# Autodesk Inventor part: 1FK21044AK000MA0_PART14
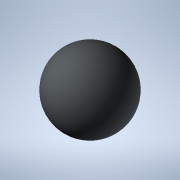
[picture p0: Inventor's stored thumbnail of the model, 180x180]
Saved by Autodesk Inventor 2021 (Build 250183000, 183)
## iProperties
Created: 2025-04
Part Number: 1FK21044AK000MA0_PART14
Material: Generic
Catalog Web Link: www.3dfindit.com
Description: -Servo synchronous motor
Document SubType Name: Modeling
Designer: psAdmin
Mass: 0.137258 g
Surface Area: 1.2868 cm^2
Volume: 0.137258 cm^3
Density: 1 g/cm^3
Appearance: PSOLRGB-212-217-219
Category: PARTsolutions
Title: 1FK21044AK000MA0_PART14
Author: Cadenas PARTsolutions
Comments: Servo synchronous motor
Sending System: PARTsolutions
Preprocessor: ST-DEVELOPER v19.3
PSOL_IDENT_0: {$CADENAS_DATA/23d-libs/siemens_ag/_cat_/87/f4/1fk21044ak000ma0.prj},216 {VTYP=3D},{NB=1FK21044AK000
PSOL_IDENT_1: MA0_PART14},{LINA=1FK21044AK000MA0_PART14},{NN=1FK21044AK000MA0_PART14},{NOPRJ=TRUE},{DATE=19.08.202
PSOL_IDENT_2: 5 14:00:48},{GEOMDATE=30.07.2025 02:00:50},{VERSION=},{LINEID=10},{WBVAR=},{WBNUMERIC=}  {NB=1FK2104
PSOL_IDENT_3: 4AK000MA0_PART14},{LINA=1FK21044AK000MA0_PART14},{KT=DUMMY},{PREVIEW=../../../_pool_/cb/72/p_d211_xx
PSOL_IDENT_4: _00434j.png},{DESCSHORT=SIMOTICS S-1FK2 HD, SINAMICS S210 3AC 400V-480V, 0.95 Nm, 6000 rpm},{DESCLON
PSOL_IDENT_5: G=SIMOTICS S-1FK2 HD servo motor M0=1.27 Nm; PN = 0.6 kW at nN=6000 rpm (380-480 V); PN = 0.4 kW at
PSOL_IDENT_6: nN=3000 rpm (200-240 V); degree of protection IP64; cylindrical shaft D19x40mm; absolute encoder 22-
PSOL_IDENT_7: bit + 12-bit multiturn (encoder AM22DQC); with OCC interface; plug size M17, rotatable; SIMOTICS S-1
PSOL_IDENT_8: FK2 servomotorfor a wide range of uses in industrial environments. SIMOTICS S‑1FK2 servomotors are c
PSOL_IDENT_9: ompact synchronous motors with a high dynamic performance that set themselves apart as a result of t
PSOL_IDENT_10: heir high power density, degree of protection and overload capability. The motors are available in t
PSOL_IDENT_11: wo variants: as High Dynamic variant (highest dynamic performance as a result of the low intrinsic m
PSOL_IDENT_12: oment of inertia for applications demanding a high dynamic performance with low moved masses) - and
PSOL_IDENT_13: as Compact variant (precise and stable closed-loop control for medium up to large moved masses as a
PSOL_IDENT_14: result of a medium intrinsic moment of inertia). SIMOTICSS‑1FK2 servomotors fully exploit their stre
PSOL_IDENT_15: ngths in a system with the SINAMICSS210 frequency converter and simple connection using the one cabl
PSOL_IDENT_16: e connection (OCC). Advantages include the short control and positioning times, fast and precise cor
PSOL_IDENT_17: rection of disturbing quantities as well as stable control with a high dynamic performance. The serv
PSOL_IDENT_18: o motors can be configured to address a wide range of requirements. For example with and without hol
PSOL_IDENT_19: ding brake, IP64 or IP65 degree of protection, singleturn or multiturn absolute encoders - to name j
PSOL_IDENT_20: ust a few. Further, the servomotors are available in different shaft heights extending from 20 to 10
PSOL_IDENT_21: 0. A shaft sealing ring is available to achieve an IP65 degree of protection and for subsequent moun
PSOL_IDENT_22: ting at the motor or as spare part. SIMOTICS - the optimum motor for each and every motion control a
PSOL_IDENT_23: pplication.},{INTNO=195125056312},{SUPPLIERALTNO=1FK2104-4AK00-0MA0},{MANUID=1FK21044AK000MA0},{MANU
PSOL_IDENT_24: NAME=Siemens},{MANUTYPEDESC=Synchronous motor 1FK2-HD 1,27 Nm},{AAU732=SIMOTICS},{AAO057=S-1FK2},{AA
PSOL_IDENT_25: U734=SIMOTICS S-1FK2 HD servo motor M0=1.27 Nm; PN = 0.6 kW at nN=6000 rpm (380-480 V); PN = 0.4 kW
PSOL_IDENT_26: at nN=3000 rpm (200-240 V); degree of protection IP64; cylindrical shaft D19x40mm; absolute encoder
PSOL_IDENT_27: 22-bit + 12-bit multiturn (encoder AM22DQC); with OCC interface; plug size M17, rotatable;},{AAW338=
PSOL_IDENT_28: Synchronous motor 1FK2-HD 1,27 Nm},{AAO742=SIMOTICS},{AAO663=4042948690994},{NOCUPEROU=1},{PRICEQUAN
PSOL_IDENT_29: TITY=1},{QUANTITYMIN=1},{QUANTITYINT=1},{CTN=85015100},{COO=DE},{AAO676=1FK2104-4AK00-0MA0},{AAO677=
PSOL_IDENT_30: Siemens AG},{ORDERUNIT=C62},{CONTENTUNIT=C62}
NB: 1FK21044AK000MA0_PART14
NT: Servo synchronous motor
NBSYN: $MANUID._PART14
LINA: 1FK21044AK000MA0_PART14
CATALOG: SIEMENS
PREVIEW: ../../../_pool_/cb/72/p_d211_xx_00434j.png
DESCSHORT: SIMOTICS S-1FK2 HD, SINAMICS S210 3AC 400V-480V, 0.95 Nm, 6000 rpm
DESCLONG: SIMOTICS S-1FK2 HD servo motor M0=1.27 Nm; PN = 0.6 kW at nN=6000 rpm (380-480 V); PN = 0.4 kW at nN=3000 rpm (200-240 V); degree of protection IP64; cylindrica
INTNO: 195125056312
SUPPLIERALTNO: 1FK2104-4AK00-0MA0
MANUID: 1FK21044AK000MA0
MANUNAME: Siemens
MANUTYPEDESC: Synchronous motor 1FK2-HD 1,27 Nm
AAU732: SIMOTICS
AAO057: S-1FK2
AAU734: SIMOTICS S-1FK2 HD servo motor M0=1.27 Nm; PN = 0.6 kW at nN=6000 rpm (380-480 V); PN = 0.4 kW at nN=3000 rpm (200-240 V); degree of protection IP64; cylindrica
AAW338: Synchronous motor 1FK2-HD 1,27 Nm
AAO742: SIMOTICS
AAO663: 4042948690994.0
NOCUPEROU: 1
PRICEQUANTITY: 1
QUANTITYMIN: 1
QUANTITYINT: 1
CTN: 85015100
COO: DE
ARTICLENO: 1FK21044AK000MA0_PART14
BOMINFO: 1FK21044AK000MA0_PART14
CREATOR: CADENAS GmbH
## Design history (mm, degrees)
feature "2025_04_17_15_37_40_0588"
body "Solid1"
